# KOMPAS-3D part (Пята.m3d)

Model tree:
1. Эскиз:1
2. Операция выдавливания:1
     Расстояние 1 = 30; Расстояние 2 = 29
3. Эскиз:2
4. Вырезать элемент выдавливания:1
     Расстояние 1 = 29
5. Эскиз:3
6. Вырезать элемент выдавливания:2
     Расстояние 1 = 2
7. Эскиз:4
8. Вырезать элемент выдавливания:3
     Расстояние 1 = 21
9. Эскиз:5
10. Вырезать элемент выдавливания:4
     Расстояние 1 = 17
11. Фаска:1
     Угол = 45; Длина 1 = 0.5; Длина 2 = 0.5
12. Эскиз:6
13. Вырезать элемент вращения:1
     Угол 1 = 360
